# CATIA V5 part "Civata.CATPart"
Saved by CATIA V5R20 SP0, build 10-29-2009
Part number: Part1.1
Bounding box of the stored display mesh (mm): x 0 to 53, y -10.97 to 10.97, z -9.5 to 9.5
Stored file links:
  C:\Users\metin\Desktop\CatiaDers\Civata.CATPart
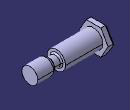
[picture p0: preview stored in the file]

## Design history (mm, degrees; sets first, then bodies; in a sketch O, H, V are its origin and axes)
Body1 (main body)
  Sketch1 on yz-plane, origin (0, 0, 0), H (0, 1, 0), V (0, 0, 1)
    point P1 (5.4848, -9.5)
    point P2 (10.9697, 0)
    point P3 (5.4848, 9.5)
    point P4 (-5.4848, 9.5)
    point P5 (-10.9697, 0)
    point P6 (-5.4848, -9.5)
    point P7 (8.2272, -4.75)
    line L1 (5.4848, -9.5) -> (10.9697, 0)
    line L2 (10.9697, 0) -> (5.4848, 9.5)
    line L3 (5.4848, 9.5) -> (-5.4848, 9.5)
    line L4 (-5.4848, 9.5) -> (-10.9697, 0)
    line L5 (-10.9697, 0) -> (-5.4848, -9.5)
    line L6 (-5.4848, -9.5) -> (5.4848, -9.5)
    construction line L7 (0, 0) -> (8.2272, -4.75)
    construction circle A1 centre (0, 0) radius 10.9697
    construction arc A2 centre (-10.9697, 0) radius 10.9697 from (-5.4848, 9.5) to (-5.4848, -9.5) cw
    construction arc A3 centre (10.9697, 0) radius 10.9697 from (5.4848, 9.5) to (5.4848, -9.5) ccw
    distance L3 L6 = 19
    coincidence: A1 P1, A1 P2, A1 P3, A1 P4, A1 P5, A1 P6, A2 O, A3 O, P2 H
    midpoint: P7 L1
    parallelism: L1 L4
  Pad1: profile Sketch1, direction (1, 0, 0), length 5
  Chamfer1: length 1.5, angle 45, on edge [start face of Pad1 | face of Pad1 from Sketch1.L3]; edge [start face of Pad1 | face of Pad1 from Sketch1.L2]; edge [start face of Pad1 | face of Pad1 from Sketch1.L6]; edge [start face of Pad1 | face of Pad1 from Sketch1.L5]
  Sketch2 on end face of Pad1, origin (5, 0, 0), H (0, 1, 0), V (0, 0, 1)
    circle A1 centre (0, 0) radius 7
    radius A1 = 7
  Pad2: profile Sketch2, direction (1, 0, 0), length 28
  Sketch3 on end face of Pad2, origin (33, 0, 0), H (0, 1, 0), V (0, 0, 1)
    circle A1 centre (0, 0) radius 6
    radius A1 = 6
  Pad3: profile Sketch3, direction (1, 0, 0), length 20
  Sketch4 on end face of Pad2, origin (33, 0, 0), H (0, 1, 0), V (0, 0, 1)
    circle A1 centre (0, 0) radius 4
    radius A1 = 4
  Pocket1: profile Sketch4, direction (1, 0, 0), length 6.3, outer side
  Fillet1: radius 1, on edge [face of Pocket1 from Sketch4.A1 | end face of Pocket1]
  Chamfer2: length 1, angle 60, on edge [end face of Pocket1 | face of Pad3 from Sketch3.A1]
  Fillet2: radius 1, on edge [face of Pocket1 | face of Pocket1 from Sketch4.A1]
